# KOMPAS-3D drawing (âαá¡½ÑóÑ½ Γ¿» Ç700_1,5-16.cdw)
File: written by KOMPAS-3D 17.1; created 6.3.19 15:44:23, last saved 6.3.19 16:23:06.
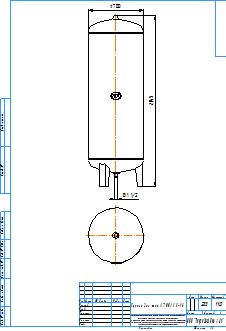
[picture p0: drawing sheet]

Sheet 1: A3, portrait

Title block, sheet 1: name: Гранлевел тип А700/1,5-16; material: Сталь 10  ГОСТ 1050-88; mass: 233; sheets: 1; sheet format: A3; stored path: C:\Users\kka\KOMPAS_Work\!Trash\ГРАНЛЕВЕЛ тип А Расширительный бак\KOMPAS 2D\Гранлевел тип А700_1,5-16.cdw

Views: Вид 1, Проекционный вид 2
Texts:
  kka
  adl
  Рама для чертежей
  Лит-Масса-Масштаб
  Материал-Предприятие
  Масштаб
  Изм.
  Лист
  № докум.
  Подп.
  Дата
  Лит.
  Разраб.
  Пров.
  Т.контр.
  Листов
  Внимание! Данный продукт является объектом авторского права ООО «Торговый Дом АДЛ».
  Запрещается изменение, копирование, распространение
  (в том числе путем копирования на другие сайты и ресурсы в Интернете)
  или любое иное использование информации и объектов без предварительного
  согласия правообладателя (ООО «Торговый Дом АДЛ»).
  Н.контр.
  Утв.
  ООО "Торговый дом АДЛ"
  Изменение
  Номер документа
  Подпись
  Обозначение документа
  Наименование изделия
  Масса изделия по ГОСТ 2.109-73
  Порядковый номер листа
  Общее количество листов в документе
  Характер работы, выполненной лицом, подписавшим документ
  Наименование или индекс предприятия, выпускающего документ
  Инв. № подл.
  Подп. и дата
  Взам. инв. №
  Инв. № дубл.
  Инвентарный номер подлинника по ГОСТ 2.501-68
  Подпись принявшего подлинник в отдел технической документации
  Инвентарный номер подлинника, взамен которого выпущен данный подлинник
  Инвентарный номер дубликата по ГОСТ 2.502-68
  Подпись принявшего дубликат в отдел технической документации
  Справ. №
  Перв. примен.
  Обозначение документа, взамен или на основании которого выпущен данный документ
  Обозначение документа, в котором впервые записан данный документ
  Подпись лица, копировавшего чертеж
  Обозначение формата листа
  !Рама для чертежа
Dimensions and other numbers on the sheet: 2145; 700; 1 1/2; 1:10; 1; 233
